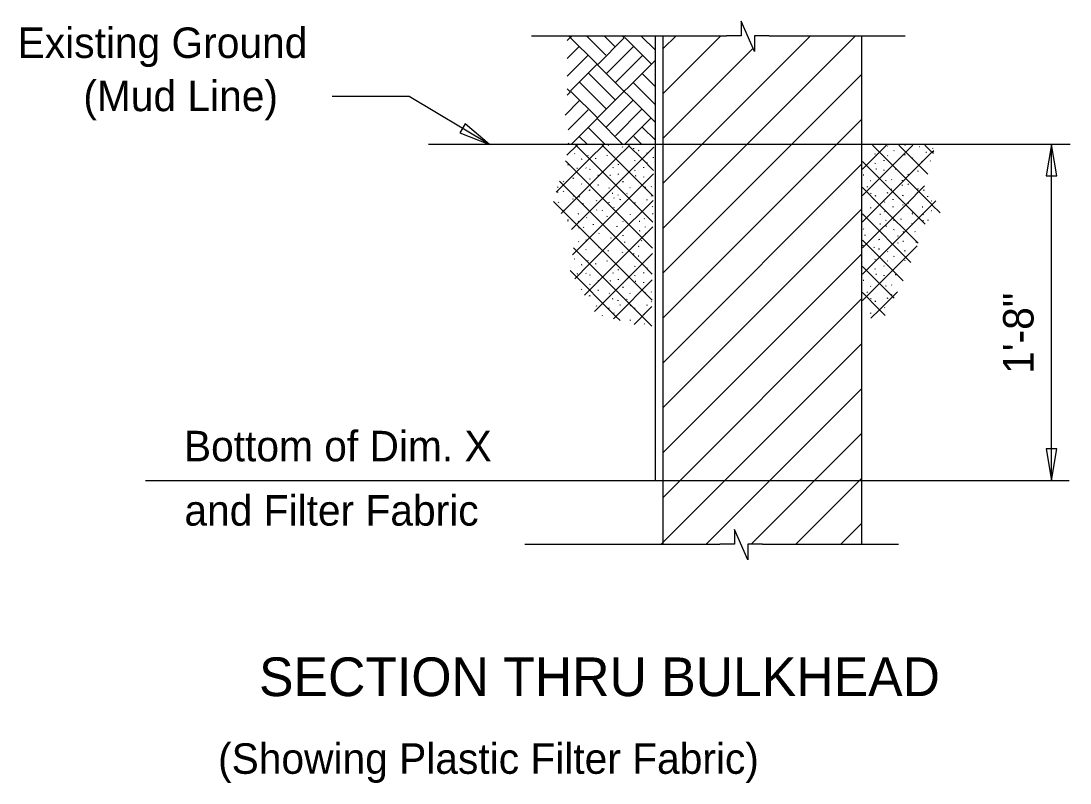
# Model space of a CAD drawing. Extents: x 0.4 to 30.4, y 0.1 to 19.4.
# Drawn here: x 9.23 to 14.44, y 10.49 to 14.27 of the extents above; entities that cross this region are included whole.
import ezdxf

# ---------------------------------------------------------------- set-up
doc = ezdxf.new("R2010")
doc.units = 0
for name, color, linetype in [('Dimension', 7, 'Continuous'), ('Miscellaneous', 7, 'Continuous'), ('Rebar', 7, 'Continuous'), ('SheetPileConc', 7, 'Continuous'), ('TextStructures', 7, 'Continuous')]:
    doc.layers.add(name, color=color, linetype=linetype)

msp = doc.modelspace()

# ---------------------------------------------------------------- linework, layer by layer
at = {"layer": 'Dimension'}
for p, q in [((11.7699, 14.197), (12.738, 14.197)), ((12.9487, 14.197), (13.6252, 14.197)), ((14.3518, 11.9905), (14.3518, 13.6572)), ((9.8519, 11.9905), (14.439, 11.9905)), ((11.737, 11.6738), (12.7051, 11.6738)), ((12.9158, 11.6738), (13.5923, 11.6738))]:
    msp.add_line(p, q, dxfattribs=at)
for points in [[(12.9487, 14.197), (12.8768, 14.197), (12.8768, 14.1188), (12.8099, 14.27), (12.8099, 14.197), (12.738, 14.197)], [(11.5605, 13.6572), (11.1618, 13.8946), (10.7797, 13.8946)], [(12.9158, 11.6738), (12.8439, 11.6738), (12.8439, 11.5957), (12.777, 11.7469), (12.777, 11.6738), (12.7051, 11.6738)]]:
    msp.add_lwpolyline(points, dxfattribs=at)
for points in [[(11.5605, 13.6572), (11.4399, 13.7599), (11.4128, 13.7144)], [(14.3517, 13.6572), (14.3253, 13.501), (14.3782, 13.501)], [(14.3517, 11.9906), (14.3782, 12.1468), (14.3253, 12.1468)]]:
    msp.add_lwpolyline(points, close=True, dxfattribs=at)
at = {"layer": 'Miscellaneous'}
for p, q in [((11.9706, 14.197), (11.9466, 14.1729)), ((12.0946, 14.0559), (11.9534, 14.197)), ((12.042, 14.197), (12.1388, 14.1002)), ((12.23, 14.1858), (12.0974, 14.0531)), ((12.1302, 14.197), (12.1829, 14.1443)), ((12.2188, 14.197), (12.2272, 14.1886)), ((12.2357, 14.197), (12.23, 14.1913)), ((12.365, 14.0563), (12.2328, 14.1886)), ((12.3842, 14.1253), (12.3126, 14.197)), ((12.4236, 13.2427), (13.378, 14.197)), ((12.4236, 13.9109), (12.7097, 14.197)), ((12.4236, 13.4654), (13.1552, 14.197)), ((12.4236, 14.1336), (12.487, 14.197)), ((12.0062, 14.1443), (11.9466, 14.0847)), ((12.2743, 14.1415), (12.1416, 14.0088)), ((12.4236, 13.6881), (12.8699, 14.1345)), ((12.0503, 14.1002), (11.9466, 13.9964)), ((12.3842, 14.0756), (12.0975, 13.7887)), ((12.3184, 14.0974), (12.1857, 13.9647)), ((12.0946, 14.0559), (11.9624, 13.9238)), ((12.3842, 13.7662), (12.0974, 14.0531)), ((12.1416, 13.8329), (12.0093, 13.9651)), ((12.1859, 13.8772), (12.0536, 14.0094)), ((12.2739, 13.9651), (12.3842, 13.8547)), ((12.318, 14.0093), (12.3842, 13.943)), ((12.4236, 13.0199), (13.408, 14.0043)), ((11.9466, 13.9341), (11.9597, 13.921)), ((11.9624, 13.9182), (11.9466, 13.9023)), ((12.0975, 13.7887), (11.9652, 13.921)), ((12.0067, 13.8739), (11.9361, 13.8033)), ((12.2737, 13.8768), (12.1416, 13.7446)), ((12.0509, 13.8298), (11.9512, 13.7301)), ((12.3178, 13.8326), (12.1857, 13.7005)), ((12.0947, 13.7859), (11.9661, 13.6572)), ((12.0947, 13.7859), (12.2234, 13.6572)), ((12.3621, 13.7883), (12.2311, 13.6572)), ((12.4236, 12.7972), (13.408, 13.7816)), ((12.0504, 13.7417), (12.1348, 13.6572)), ((12.3842, 13.6788), (12.3212, 13.7419)), ((14.4433, 13.6572), (11.2587, 13.6572)), ((11.9455, 13.6035), (11.9975, 13.6555)), ((11.958, 13.6572), (11.9512, 13.6641)), ((12.0578, 13.5856), (11.9878, 13.6556)), ((12.0063, 13.6976), (12.0466, 13.6572)), ((12.0578, 13.5856), (12.1264, 13.6541)), ((12.1878, 13.5858), (12.1194, 13.6542)), ((12.1523, 13.6532), (12.1486, 13.6525)), ((12.1881, 13.5856), (12.2553, 13.6528)), ((12.2215, 13.6441), (12.2223, 13.6472)), ((12.3183, 13.5856), (12.251, 13.6529)), ((12.3172, 13.6572), (12.2769, 13.6976)), ((13.4129, 13.5345), (13.5321, 13.6537)), ((13.4129, 13.4043), (13.6623, 13.6537)), ((13.7576, 13.3588), (13.4626, 13.6537)), ((13.538, 13.6483), (13.5372, 13.6498)), ((13.7367, 13.5099), (13.5928, 13.6537)), ((13.6237, 13.6521), (13.624, 13.6537)), ((13.7578, 13.6189), (13.723, 13.6537)), ((11.9851, 13.6111), (11.9836, 13.6118)), ((12.0513, 13.6028), (12.0506, 13.6043)), ((12.1455, 13.6023), (12.1463, 13.6053)), ((12.1817, 13.5945), (12.1824, 13.5976)), ((12.2772, 13.6359), (12.2779, 13.6389)), ((12.3027, 13.6269), (12.2982, 13.6261)), ((12.3183, 13.5856), (12.3761, 13.6434)), ((12.3441, 13.614), (12.3434, 13.6155)), ((13.4763, 13.61), (13.4778, 13.613)), ((13.4974, 13.3585), (13.7578, 13.619)), ((13.538, 13.601), (13.5372, 13.6025)), ((13.5688, 13.6251), (13.5695, 13.6281)), ((13.6237, 13.6048), (13.6245, 13.6085)), ((13.6959, 13.6454), (13.6944, 13.6461)), ((13.7305, 13.6182), (13.7275, 13.6168)), ((13.7578, 13.6189), (13.7669, 13.628)), ((13.7646, 13.6122), (13.7578, 13.619)), ((13.7621, 13.6371), (13.7613, 13.6386)), ((11.8926, 13.4203), (12.0578, 13.5856)), ((11.9169, 13.3143), (12.1881, 13.5856)), ((12.1881, 13.3251), (11.9375, 13.5757)), ((11.9506, 13.5554), (11.9513, 13.5584)), ((12.0197, 13.584), (12.0167, 13.5825)), ((12.1881, 13.4554), (12.0578, 13.5856)), ((12.0881, 13.5862), (12.0888, 13.5892)), ((12.1749, 13.5419), (12.1757, 13.5449)), ((12.3735, 13.4001), (12.1881, 13.5856)), ((12.1881, 13.4554), (12.3183, 13.5856)), ((12.2005, 13.557), (12.2012, 13.5599)), ((12.2824, 13.5757), (12.2839, 13.5788)), ((12.3749, 13.5289), (12.3183, 13.5856)), ((12.3268, 13.5419), (12.3268, 13.5449)), ((12.3441, 13.5667), (12.3434, 13.5682)), ((12.3749, 13.5908), (12.3756, 13.5936)), ((12.4236, 12.5745), (13.408, 13.5588)), ((13.6276, 13.3585), (13.4129, 13.5732)), ((13.4763, 13.5626), (13.4778, 13.5656)), ((13.5207, 13.5762), (13.5207, 13.5792)), ((13.6613, 13.5897), (13.6621, 13.5927)), ((13.7087, 13.5724), (13.705, 13.5717)), ((13.7508, 13.5739), (13.7493, 13.5762)), ((11.9769, 13.49), (11.9784, 13.493)), ((11.9784, 13.4885), (11.9791, 13.4915)), ((11.9979, 13.5381), (11.9942, 13.5374)), ((12.04, 13.5396), (12.0385, 13.5419)), ((12.0588, 13.5329), (12.0603, 13.5359)), ((12.1022, 13.5036), (12.0984, 13.5028)), ((12.1614, 13.5036), (12.1576, 13.5028)), ((12.1881, 13.3251), (12.3747, 13.5118)), ((12.2005, 13.5088), (12.2012, 13.5118)), ((12.2824, 13.5284), (12.2839, 13.5314)), ((12.2877, 13.5013), (12.2847, 13.5006)), ((12.3268, 13.4945), (12.3268, 13.4975)), ((13.4199, 13.5055), (13.4154, 13.5055)), ((13.4816, 13.5356), (13.4786, 13.5348)), ((13.5207, 13.5288), (13.5207, 13.5318)), ((13.5793, 13.5341), (13.5756, 13.5333)), ((13.6387, 13.5063), (13.641, 13.5092)), ((13.6876, 13.5243), (13.6891, 13.5273)), ((13.6891, 13.5228), (13.6899, 13.5258)), ((11.9002, 13.4434), (11.9009, 13.4464)), ((12.1881, 13.1949), (11.9083, 13.4746)), ((11.928, 13.472), (11.9302, 13.4749)), ((11.9678, 13.235), (12.1881, 13.4554)), ((12.0197, 13.4599), (12.0182, 13.4622)), ((12.0588, 13.4855), (12.0603, 13.4885)), ((12.1022, 13.4562), (12.0984, 13.4554)), ((12.1557, 13.4404), (12.1565, 13.4434)), ((12.3721, 13.2713), (12.1881, 13.4554)), ((12.226, 13.4712), (12.2215, 13.4712)), ((12.2599, 13.4419), (12.2584, 13.4426)), ((12.335, 13.4434), (12.3358, 13.4464)), ((12.3644, 13.4479), (12.3637, 13.4494)), ((13.4974, 13.3585), (13.4129, 13.443)), ((13.4372, 13.4461), (13.438, 13.449)), ((13.4538, 13.4762), (13.4523, 13.4769)), ((13.5289, 13.4777), (13.5297, 13.4807)), ((13.5583, 13.4822), (13.5576, 13.4837)), ((13.6109, 13.4777), (13.6117, 13.4807)), ((13.6109, 13.4536), (13.6117, 13.4566)), ((13.6276, 13.3585), (13.7209, 13.4518)), ((13.6387, 13.4589), (13.641, 13.4619)), ((11.9002, 13.4193), (11.9009, 13.4223)), ((11.928, 13.4246), (11.9302, 13.4276)), ((11.9746, 13.3855), (11.9761, 13.3886)), ((11.9784, 13.4013), (11.9791, 13.4043)), ((12.0069, 13.3952), (12.0084, 13.399)), ((12.058, 13.4276), (12.0573, 13.4291)), ((12.0611, 13.4299), (12.058, 13.4299)), ((12.1734, 13.414), (12.1697, 13.4133)), ((12.1802, 13.3915), (12.1798, 13.3923)), ((12.199, 13.405), (12.1997, 13.4081)), ((12.2103, 13.3832), (12.2118, 13.387)), ((12.2434, 13.4118), (12.2441, 13.4148)), ((12.3644, 13.4006), (12.3637, 13.4021)), ((13.4546, 13.4145), (13.4561, 13.4175)), ((13.4786, 13.4017), (13.4749, 13.4009)), ((13.538, 13.4175), (13.5343, 13.416)), ((13.5583, 13.4348), (13.5576, 13.4363)), ((13.6139, 13.4032), (13.6155, 13.4069)), ((13.6854, 13.4198), (13.6869, 13.4228)), ((13.6891, 13.4356), (13.6899, 13.4386)), ((13.7177, 13.4295), (13.7192, 13.4333)), ((13.7372, 13.3972), (13.738, 13.4002)), ((12.1878, 13.0649), (11.8791, 13.3736)), ((11.9032, 13.369), (11.9047, 13.3727)), ((12.0265, 13.3629), (12.0272, 13.366)), ((12.0446, 13.3412), (12.0423, 13.3419)), ((12.0919, 13.378), (12.0934, 13.381)), ((12.1542, 13.3675), (12.1549, 13.3705)), ((12.1802, 13.3442), (12.1794, 13.3456)), ((12.1881, 13.1949), (12.3733, 13.3801)), ((12.2607, 13.3802), (12.2622, 13.3832)), ((12.2847, 13.3675), (12.281, 13.3667)), ((12.3306, 13.3359), (12.3283, 13.3382)), ((12.3441, 13.3832), (12.3404, 13.3817)), ((12.3704, 13.3487), (12.3712, 13.3516)), ((12.4236, 12.3517), (13.408, 13.3361)), ((13.4129, 13.0136), (13.7578, 13.3585)), ((13.4129, 13.274), (13.4974, 13.3585)), ((13.4129, 13.1438), (13.6276, 13.3585)), ((13.4541, 13.3419), (13.4549, 13.3448)), ((13.6887, 13.1672), (13.4974, 13.3585)), ((13.5245, 13.3702), (13.5222, 13.3724)), ((13.5643, 13.383), (13.5651, 13.3859)), ((13.5651, 13.3461), (13.5658, 13.3491)), ((13.6139, 13.3558), (13.6155, 13.3596)), ((13.724, 13.2621), (13.6276, 13.3585)), ((13.641, 13.3642), (13.6417, 13.3671)), ((13.7132, 13.3468), (13.7094, 13.3461)), ((13.7553, 13.3754), (13.7531, 13.3761)), ((13.7578, 13.3585), (13.7772, 13.3779)), ((13.7979, 13.3184), (13.7578, 13.3585)), ((11.9302, 13.3299), (11.931, 13.3328)), ((11.9506, 13.2817), (11.9513, 13.2848)), ((11.9722, 13.1093), (12.1881, 13.3251)), ((12.0024, 13.3125), (11.9986, 13.3118)), ((12.0446, 13.2938), (12.0423, 13.2945)), ((12.0919, 13.3306), (12.0934, 13.3336)), ((12.1214, 13.3289), (12.1221, 13.332)), ((12.1452, 13.3007), (12.1459, 13.3037)), ((12.3707, 13.1425), (12.1881, 13.3251)), ((12.2602, 13.3076), (12.261, 13.3106)), ((12.3306, 13.2886), (12.3283, 13.2908)), ((12.3712, 13.3118), (12.3719, 13.3149)), ((13.6536, 13.072), (13.4129, 13.3127)), ((13.4184, 13.3069), (13.4191, 13.31)), ((13.5019, 13.31), (13.4981, 13.3092)), ((13.5245, 13.3228), (13.5222, 13.325)), ((13.5289, 13.2806), (13.5297, 13.2837)), ((13.5688, 13.2806), (13.5695, 13.2837)), ((13.6041, 13.2856), (13.6049, 13.2885)), ((13.6598, 13.3107), (13.6613, 13.3138)), ((13.6613, 13.316), (13.6621, 13.319)), ((13.7143, 13.309), (13.715, 13.312)), ((13.7387, 13.2799), (13.7395, 13.2829)), ((13.7553, 13.328), (13.7531, 13.3288)), ((11.949, 13.2764), (11.9506, 13.2795)), ((12.0054, 13.2442), (12.0024, 13.2434)), ((12.0035, 13.2748), (12.0043, 13.2777)), ((12.028, 13.2456), (12.0287, 13.2486)), ((12.0769, 13.2592), (12.0776, 13.2622)), ((12.123, 13.257), (12.1245, 13.26)), ((12.1881, 13.0647), (12.3718, 13.2485)), ((12.1945, 13.2486), (12.1952, 13.2516)), ((12.2245, 13.2727), (12.2253, 13.2757)), ((12.308, 13.2757), (12.3042, 13.2749)), ((12.335, 13.2464), (12.3358, 13.2494)), ((13.4184, 13.2378), (13.4191, 13.2408)), ((13.5019, 13.2627), (13.4981, 13.2619)), ((13.5315, 13.2504), (13.5322, 13.2534)), ((13.5688, 13.2333), (13.5695, 13.2363)), ((13.6598, 13.2634), (13.6613, 13.2664)), ((13.7162, 13.2784), (13.7132, 13.2776)), ((12.0415, 13.1832), (12.0385, 13.1817)), ((12.0578, 13.0647), (12.1881, 13.1949)), ((12.1036, 13.2149), (12.1051, 13.2178)), ((12.1644, 13.1915), (12.1629, 13.1938)), ((12.3183, 13.0647), (12.1881, 13.1949)), ((12.2245, 13.2035), (12.2253, 13.2065)), ((12.308, 13.2284), (12.3042, 13.2276)), ((12.3163, 13.1795), (12.3171, 13.1824)), ((12.3376, 13.2162), (12.3383, 13.2191)), ((13.6145, 12.9809), (13.4129, 13.1825)), ((13.426, 13.2058), (13.4268, 13.2088)), ((13.4966, 13.1851), (13.4921, 13.1844)), ((13.5102, 13.2138), (13.5109, 13.2167)), ((13.5891, 13.2025), (13.5899, 13.2054)), ((13.6169, 13.2235), (13.6139, 13.2228)), ((13.6749, 13.2235), (13.6726, 13.2258)), ((12.0578, 13.0647), (11.9775, 13.1451)), ((12.0032, 13.1734), (12.0047, 13.1764)), ((12.0415, 13.1358), (12.0385, 13.1344)), ((12.1052, 13.1442), (12.1037, 13.1464)), ((12.1523, 13.1299), (12.1486, 13.1291)), ((12.2321, 13.1716), (12.2329, 13.1745)), ((12.3027, 13.1509), (12.2982, 13.1501)), ((13.4129, 12.8834), (13.684, 13.1545)), ((13.4154, 13.1551), (13.4162, 13.1581)), ((13.4711, 13.1468), (13.4718, 13.1498)), ((13.4966, 13.1378), (13.4921, 13.137)), ((13.538, 13.125), (13.5372, 13.1265)), ((13.5891, 13.1671), (13.5899, 13.1701)), ((13.6169, 13.1761), (13.6139, 13.1754)), ((13.6237, 13.1287), (13.6245, 13.1325)), ((13.6801, 13.1717), (13.6809, 13.1746)), ((11.9851, 13.0878), (11.9836, 13.0885)), ((12.0513, 13.0794), (12.0506, 13.0809)), ((12.1455, 13.0789), (12.1463, 13.0819)), ((12.1817, 13.0712), (12.1824, 13.0742)), ((12.2215, 13.1208), (12.2223, 13.1238)), ((12.2772, 13.1125), (12.2779, 13.1156)), ((12.3027, 13.1035), (12.2982, 13.1027)), ((12.3183, 13.0647), (12.3704, 13.1168)), ((12.3441, 13.0907), (12.3434, 13.0922)), ((12.4236, 12.129), (13.408, 13.1133)), ((13.4763, 13.0866), (13.4778, 13.0897)), ((13.538, 13.0776), (13.5372, 13.0791)), ((13.5688, 13.1017), (13.5695, 13.1047)), ((13.6237, 13.0814), (13.6245, 13.0851)), ((12.1881, 12.8042), (11.9608, 13.0315)), ((11.9843, 12.9911), (12.0578, 13.0647)), ((12.0197, 13.0606), (12.0167, 13.0592)), ((12.0331, 12.9097), (12.1881, 13.0647)), ((12.1881, 12.9345), (12.0578, 13.0647)), ((12.0881, 13.0629), (12.0888, 13.0659)), ((12.3679, 12.8848), (12.1881, 13.0647)), ((12.1881, 12.9345), (12.3183, 13.0647)), ((12.2005, 13.0336), (12.2012, 13.0366)), ((12.2824, 13.0524), (12.2839, 13.0554)), ((12.3693, 13.0136), (12.3183, 13.0647)), ((12.3441, 13.0434), (12.3434, 13.0449)), ((13.57, 12.8952), (13.4129, 13.0523)), ((13.4763, 13.0393), (13.4778, 13.0423)), ((13.5207, 13.0528), (13.5207, 13.0558)), ((11.9979, 13.0148), (11.9942, 13.0141)), ((12.04, 13.0163), (12.0385, 13.0186)), ((12.0588, 13.0095), (12.0603, 13.0125)), ((12.1022, 12.9802), (12.0984, 12.9794)), ((12.1614, 12.9802), (12.1576, 12.9794)), ((12.1749, 13.0186), (12.1757, 13.0216)), ((12.1881, 12.8042), (12.369, 12.9851)), ((12.2005, 12.9854), (12.2012, 12.9885)), ((12.2824, 13.005), (12.2839, 13.008)), ((12.2877, 12.9779), (12.2847, 12.9772)), ((12.3268, 13.0186), (12.3268, 13.0216)), ((12.3268, 12.9712), (12.3268, 12.9742)), ((13.4199, 12.9821), (13.4154, 12.9821)), ((13.4816, 13.0122), (13.4786, 13.0115)), ((13.5207, 13.0054), (13.5207, 13.0084)), ((13.5793, 13.0107), (13.5756, 13.0099)), ((12.0197, 12.9366), (12.0182, 12.9389)), ((12.0588, 12.9621), (12.0603, 12.9652)), ((12.0819, 12.8283), (12.1881, 12.9345)), ((12.1022, 12.9328), (12.0984, 12.932)), ((12.1557, 12.9171), (12.1565, 12.9201)), ((12.3665, 12.756), (12.1881, 12.9345)), ((12.226, 12.9479), (12.2215, 12.9479)), ((12.2599, 12.9186), (12.2584, 12.9193)), ((12.335, 12.9201), (12.3358, 12.9231)), ((12.3644, 12.9246), (12.3637, 12.9261)), ((13.4974, 12.8376), (13.4129, 12.9221)), ((13.4372, 12.9228), (13.438, 12.9257)), ((13.4538, 12.9528), (13.4523, 12.9536)), ((13.4974, 12.8376), (13.5864, 12.9266)), ((13.5289, 12.9543), (13.5297, 12.9573)), ((13.5583, 12.9588), (13.5576, 12.9603)), ((12.058, 12.9042), (12.0573, 12.9057)), ((12.0611, 12.9065), (12.058, 12.9065)), ((12.1734, 12.8907), (12.1697, 12.89)), ((12.1802, 12.8681), (12.1798, 12.869)), ((12.199, 12.8817), (12.1997, 12.8847)), ((12.2434, 12.8885), (12.2441, 12.8914)), ((12.3644, 12.8772), (12.3637, 12.8787)), ((12.4236, 11.9062), (13.408, 12.8906)), ((13.4546, 12.8911), (13.4561, 12.8941)), ((13.4786, 12.8784), (13.4749, 12.8776)), ((13.538, 12.8941), (13.5343, 12.8926)), ((13.5583, 12.9115), (13.5576, 12.913)), ((12.0919, 12.8547), (12.0934, 12.8577)), ((12.1542, 12.8441), (12.1549, 12.8472)), ((12.1802, 12.8208), (12.1794, 12.8223)), ((12.2103, 12.8599), (12.2118, 12.8636)), ((12.2607, 12.8569), (12.2622, 12.8599)), ((12.2783, 12.7642), (12.3675, 12.8535)), ((12.2847, 12.8441), (12.281, 12.8433)), ((12.3306, 12.8125), (12.3283, 12.8148)), ((12.3441, 12.8599), (12.3404, 12.8584)), ((13.4541, 12.8186), (13.4549, 12.8215)), ((13.4546, 12.7948), (13.4974, 12.8376)), ((13.5255, 12.8095), (13.4974, 12.8376)), ((13.5245, 12.8468), (13.5222, 12.8491)), ((12.1218, 12.8072), (12.1221, 12.8086)), ((12.1761, 12.7923), (12.1881, 12.8042)), ((12.2091, 12.7832), (12.1881, 12.8042)), ((12.2602, 12.7843), (12.261, 12.7872)), ((12.3306, 12.7652), (12.3283, 12.7674)), ((12.4139, 11.6738), (13.408, 12.6679)), ((12.6367, 11.6738), (13.408, 12.4451)), ((12.8594, 11.6738), (13.408, 12.2224)), ((13.0822, 11.6738), (13.408, 11.9997)), ((13.3049, 11.6738), (13.408, 11.7769))]:
    msp.add_line(p, q, dxfattribs=at)
at = {"layer": 'Rebar'}
msp.add_line((12.3842, 11.9905), (12.3842, 14.197), dxfattribs=at)
at = {"layer": 'SheetPileConc'}
for p, q in [((12.4236, 11.6738), (12.4236, 14.197)), ((13.408, 14.197), (13.408, 11.6738))]:
    msp.add_line(p, q, dxfattribs=at)

# ---------------------------------------------------------------- texts
at = {"layer": 'Dimension'}
for s, p in [('Existing Ground', (9.2178, 14.0867)), ('(Mud Line)', (9.5441, 13.8227)), ('Bottom of Dim. X', (10.0435, 12.0852)), ('and Filter Fabric', (10.046, 11.766))]:
    msp.add_text(s, height=0.1512, dxfattribs=at).set_placement(p)
at = {"layer": 'TextStructures'}
msp.add_text('1\'-8"', height=0.1512, rotation=90, dxfattribs=at).set_placement((14.2621, 12.5191))
for s, height, p in [('SECTION THRU BULKHEAD', 0.192, (10.4165, 10.92)), ('(Showing Plastic Filter Fabric)', 0.1512, (10.213, 10.5345))]:
    msp.add_text(s, height=height, dxfattribs=at).set_placement(p)

doc.saveas('drawing.dxf')
